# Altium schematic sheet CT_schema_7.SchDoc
size 287 x 160 mm
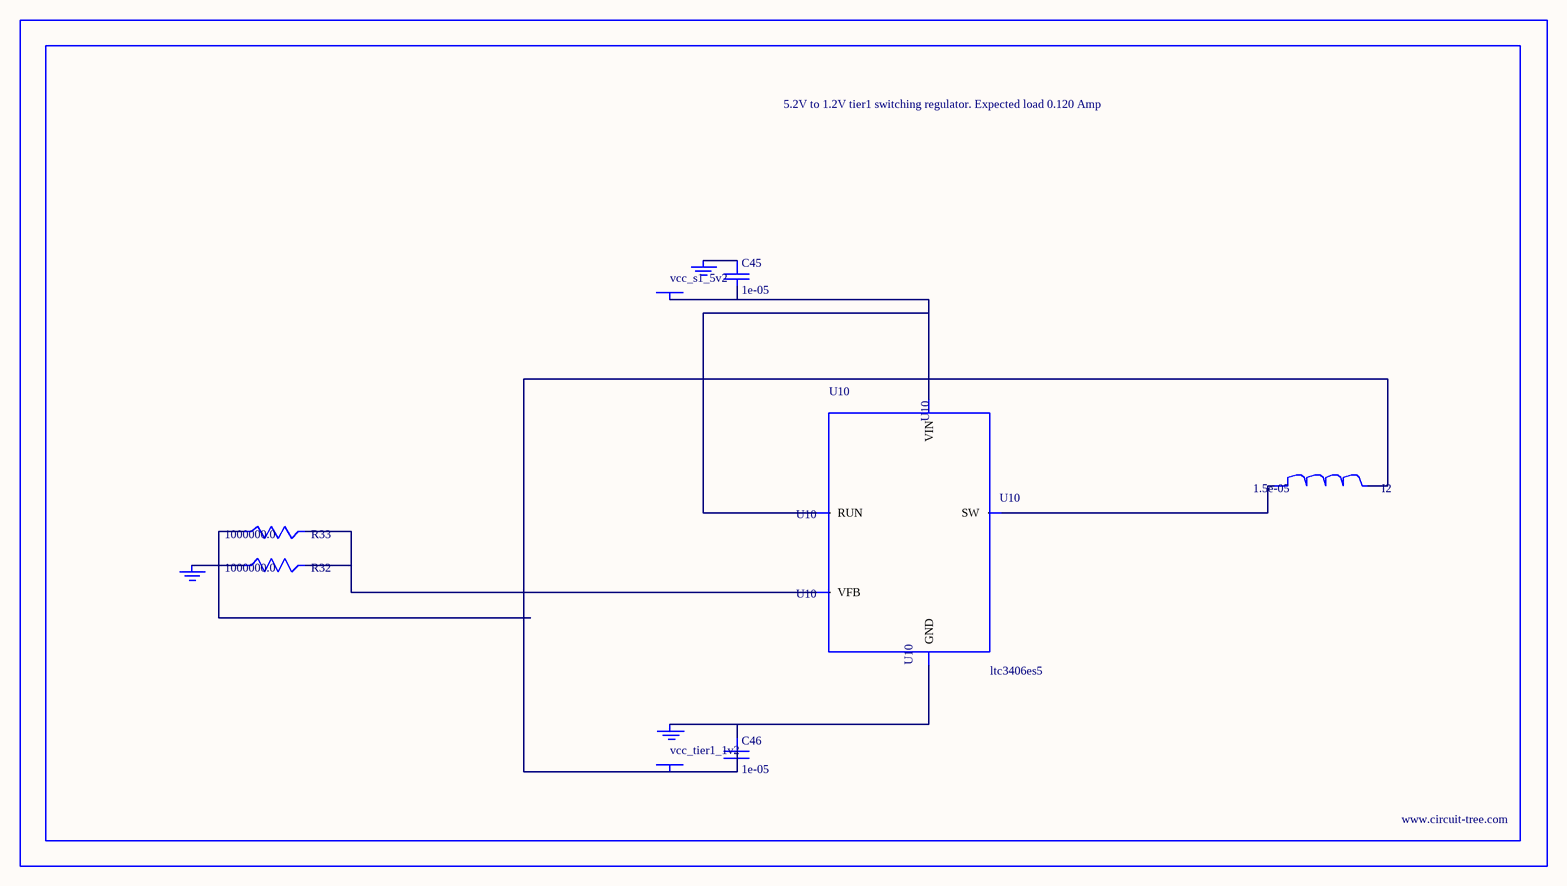
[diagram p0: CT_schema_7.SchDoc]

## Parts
BORDER6  (no value)
C45  1e-05  [C0805]
C46  1e-05  [C0805]
GND_INSTANCE_6_0  (no value)
GND_INSTANCE_6_1  (no value)
GND_INSTANCE_6_2  (no value)
I2  1.5e-05  [L1210]
POWER_INSTANCE_6_0  vcc_tier1_1v2
POWER_INSTANCE_6_1  vcc_s1_5v2
R32  1000000.0  [R0603]
R33  1000000.0  [R0603]
U10  ltc3406es5  [TSOT-23-5]

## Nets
NetC45_1: C45.1 GND_INSTANCE_6_1.0(GND)
NetC45_2: C45.2 POWER_INSTANCE_6_1.0(PWR) U10.1(RUN) U10.4(VIN)
NetC46_1: C46.1 GND_INSTANCE_6_0.0(GND) U10.2(GND)
NetC46_2: C46.2 I2.2 POWER_INSTANCE_6_0.0(PWR) R33.1
NetGND_INSTANCE_6_2_0: GND_INSTANCE_6_2.0(GND) R32.1
NetI2_1: I2.1 U10.3(SW)
NetR32_2: R32.2 R33.2 U10.5(VFB)

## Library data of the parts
BORDER6 = BORDER_PAGE6
C45 C46 = C0805C106K8RACTU
GND_INSTANCE_6_0-GND_INSTANCE_6_2 = GND
I2 = L1210R150MDWIT
POWER_INSTANCE_6_0 POWER_INSTANCE_6_1 = PWR
R32 R33 = RC0603JR-071ML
